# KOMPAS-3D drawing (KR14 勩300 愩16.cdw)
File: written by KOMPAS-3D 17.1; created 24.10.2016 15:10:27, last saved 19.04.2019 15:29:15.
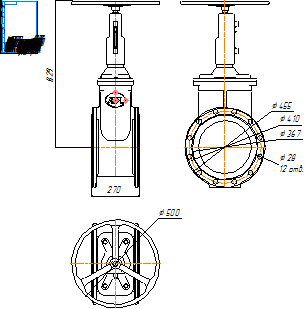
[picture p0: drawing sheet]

Sheet 1: A4, portrait

Title block, sheet 1: name: KR14 Ду300 Ру16; material: Внимание! Данный продукт является объектом авторского права ООО «Торговый Дом АДЛ». / Запрещается изменение, копирование, распространение / (в том числе путем копирования на другие сайты и ресурсы в Интернете) / или любое иное использование информации и объектов без предварительного / согласия правообладателя (ООО «Торговый Дом АДЛ»).; mass: 289,3; sheets: 1; organisation: ООО "Торговый дом АДЛ"; sheet format: A4; stored path: \\adlc.lan\data\АДЛ_ПКД\3D-модели\ADL production\Клиновые задвижки серии KR ГРАНАР\Клиновые задвижки KR14\kompas 2d\KR14 Ду300 Ру16.cdw

Views: Вид 1
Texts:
  Klimkovich
  ADL
Dimensions and other numbers on the sheet: 270; 829; 1:1; 1; 289,3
